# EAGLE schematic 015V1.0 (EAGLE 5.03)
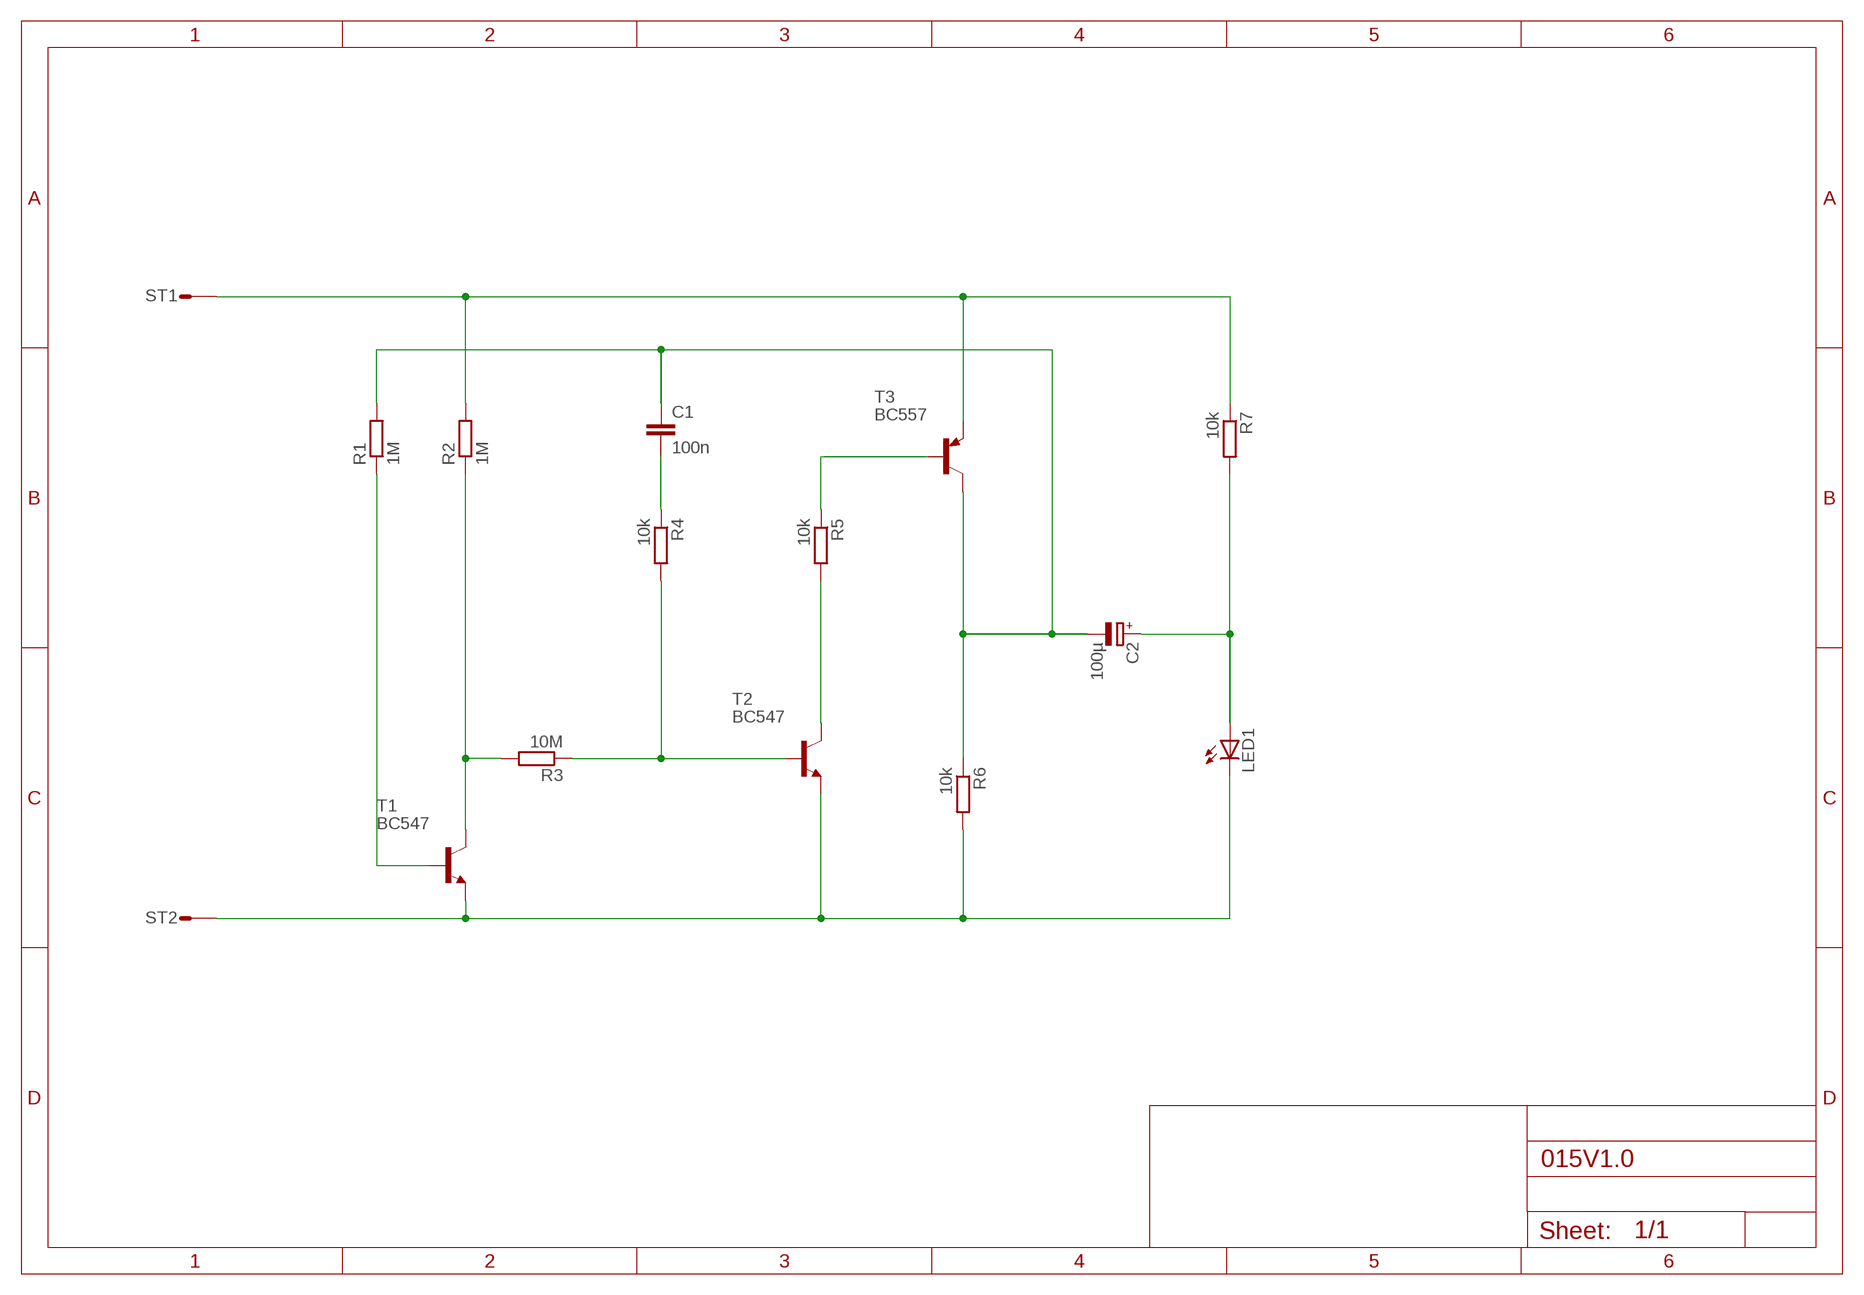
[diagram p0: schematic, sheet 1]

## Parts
C1  100n  C-EU050-024X044  [C050-024X044]
C2  100µ  CPOL-EUE3.5-8  [E3,5-8]
LED1  LED5MM  [LED5MM]
R1  1M  R-EU_0207/7  [0207/7]
R2  1M  R-EU_0207/7  [0207/7]
R3  10M  R-EU_0207/7  [0207/7]
R4  10k  R-EU_0207/7  [0207/7]
R5  10k  R-EU_0207/7  [0207/7]
R6  10k  R-EU_0207/7  [0207/7]
R7  10k  R-EU_0207/7  [0207/7]
ST1  ST2,8  [ST2,8]
ST2  ST2,8  [ST2,8]
T1  BC547  -NPN-TO92L  [TO92L]
T2  BC547  -NPN-TO92L  [TO92L]
T3  BC557  -PNP-TO92L  [TO92L]

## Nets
GND: LED1.K(C) R6.2 ST2.1(ST) T1.1(E) T2.1(E)
N$1: R2.2 R7.1 ST1.1(ST) T3.1(E)
N$2: R1.1 T1.2(B)
N$3: R2.1 R3.2 T1.3(C)
N$4: R3.1 R4.2 T2.2(B)
N$5: C1.2 R4.1
N$6: R5.2 T2.3(C)
N$7: R5.1 T3.2(B)
N$9: C2.+ LED1.A R7.2
N$10: C1.1 C2.- R1.2 R6.1 T3.3(C)

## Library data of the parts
C1 = rcl:C-EU: CAPACITOR, European symbol
C2 = rcl:CPOL-EU: POLARIZED CAPACITOR, European symbol
LED1 = led:LED: LED
R1-R7 = rcl:R-EU_: RESISTOR, European symbol
ST1 ST2 = con-rib:ST2,8: RIBBON CABLE CONNECTOR
T1 T2 = transistor-neu-to92:*-NPN-: NPN Transistror
T3 = transistor-neu-to92:*-PNP-: PNP Transistror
